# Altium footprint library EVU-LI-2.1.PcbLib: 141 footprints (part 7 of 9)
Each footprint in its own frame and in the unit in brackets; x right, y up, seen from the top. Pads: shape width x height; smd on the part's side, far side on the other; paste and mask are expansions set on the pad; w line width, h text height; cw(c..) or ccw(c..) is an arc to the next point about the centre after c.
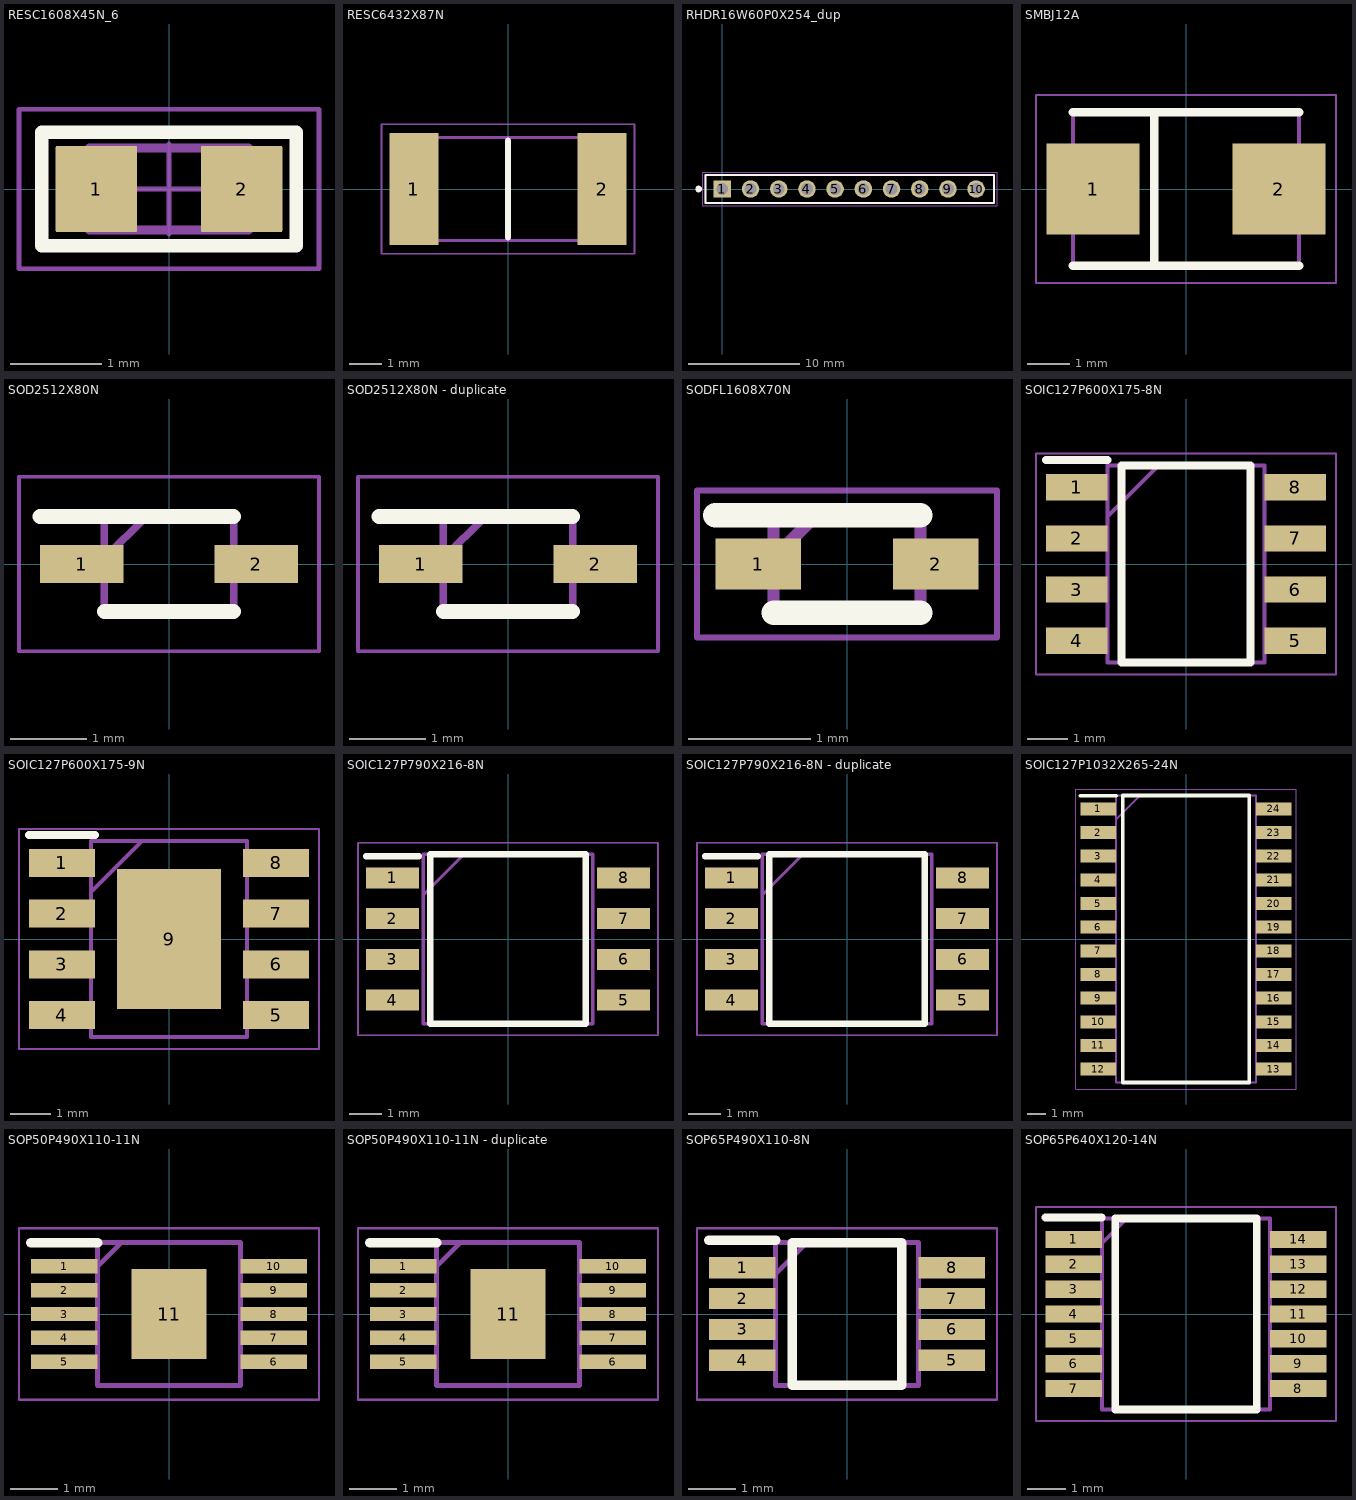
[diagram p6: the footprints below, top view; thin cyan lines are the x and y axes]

## RESC1608X45N_6 [mm]
pads (2):
  rrect5% 0.9x0.95 smd mask+0.07: 1(-0.8,0) 2(0.8,0)
Top Overlay:
  lines w0.15: -1.4,-0.625 1.4,-0.625 1.4,0.625 -1.4,0.625 -1.4,-0.625
Top Assembly:
  lines w0.1: -0.875,-0.45 -0.875,0.45 0.875,0.45 0.875,-0.45 -0.875,-0.45
Top Designator:
  text ".Designator" at -3.25,-0.3 h1.5
Mechanical 9:
  text ".MARK" at -1.725,-0.341 h1.2
Top Courtyard:
  lines w0.05: -0.5,0 0.5,0 ; 0,-0.5 0,0.5 ; -1.65,-0.875 -1.65,0.875 1.65,0.875 1.65,-0.875 -1.65,-0.875
3D body "RESC1608X06N.step": height 0.55, standoff 0, extent -0.85,-0.45 0.85,0.45

## RESC6432X87N [mm]
pads (2):
  rect 1.5x3.45 smd: 1(-2.9,0) 2(2.9,0)
Top Overlay:
  lines w0.2: 0,-1.49 0,1.49
Mechanical 13:
  lines w0.1: -3.175,-1.59 3.175,-1.59 3.175,1.59 -3.175,1.59 -3.175,-1.59
Top Courtyard:
  lines w0.05: -3.9,-2 3.9,-2 3.9,2 -3.9,2 -3.9,-2
3D body "TLR3APDTE10L0F50.stp": height 0.87, standoff 0, extent -3.175,-1.59 3.175,1.59

## RHDR16W60P0X254_dup [mm]
height 1.27
pads (10):
  rect 1.575x1.575 hole 1.05: 1(0,0)
  round 1.575 hole 1.05: 2(2.54,0) 3(5.08,0) 4(7.62,0) 5(10.16,0) 6(12.7,0) 7(15.24,0) 8(17.78,0) 9(20.32,0) 10(22.86,0)
Top Overlay:
  circle w0.3: c-2.134,0 r0.15
  lines w0.2: -1.52,-1.27 -1.52,1.27 24.46,1.27 24.46,-1.27 -1.473,-1.27
Assembly Notes:
  lines w0.1: -1.52,-1.27 -1.52,1.27 24.46,1.27 24.46,-1.27 -1.52,-1.27
Top Courtyard:
  lines w0.05: -1.77,-1.52 -1.77,1.52 24.74,1.52 24.74,-1.52 -1.77,-1.52
3D body "PBS-10.step": height 8.5, standoff -3, extent -1.469,-1.199 24.431,1.301

## SMBJ12A [mm]
pads (2):
  rect 2.2x2.15 smd: 1(-2.2,0) 2(2.2,0)
Top Overlay:
  lines w0.2: -2.675,-1.812 2.675,-1.812 ; -2.675,1.812 2.675,1.812 ; -0.75,-1.812 -0.75,1.812
Mechanical 13:
  lines w0.1: -2.675,-1.812 -2.675,1.812 2.675,1.812 2.675,-1.812 -2.675,-1.812
Top Courtyard:
  lines w0.05: -3.55,-2.225 -3.55,2.225 3.55,2.225 3.55,-2.225 -3.55,-2.225
3D body "SMBJ48A-TR.stp": height 2.33, standoff 0.01, extent -2.675,-1.86 2.675,1.86

## SOD2512X80N [mm]
pads (2):
  rect 1.1x0.5 smd: 1(-1.15,0) 2(1.15,0)
Top Overlay:
  lines w0.2: -1.7,0.625 0.85,0.625 ; -0.85,-0.625 0.85,-0.625
Mechanical 13:
  lines w0.1: -0.85,0.075 -0.3,0.625 ; -0.85,-0.625 -0.85,0.625 0.85,0.625 0.85,-0.625 -0.85,-0.625
Top Courtyard:
  lines w0.05: -1.975,-1.15 -1.975,1.15 1.975,1.15 1.975,-1.15 -1.975,-1.15
3D body "BZX84J-B4V7.stp": height 0.8, standoff 0, extent -1.25,-0.625 1.25,0.625

## SOD2512X80N - duplicate [mm]
pads (2):
  rect 1.1x0.5 smd: 1(-1.15,0) 2(1.15,0)
Top Overlay:
  lines w0.2: -1.7,0.625 0.85,0.625 ; -0.85,-0.625 0.85,-0.625
Mechanical 13:
  lines w0.1: -0.85,0.075 -0.3,0.625 ; -0.85,-0.625 0.85,-0.625 0.85,0.625 -0.85,0.625 -0.85,-0.625
Top Courtyard:
  lines w0.05: -1.975,-1.15 1.975,-1.15 1.975,1.15 -1.975,1.15 -1.975,-1.15
3D body "BZX84J-B4V7.stp": height 0.8, standoff 0, extent -1.25,-0.625 1.25,0.625

## SODFL1608X70N [mm]
pads (2):
  rect 0.7x0.42 smd: 1(-0.725,0) 2(0.725,0)
Top Overlay:
  lines w0.2: -1.075,0.4 0.6,0.4 ; -0.6,-0.4 0.6,-0.4
Mechanical 13:
  lines w0.1: -0.6,0.05 -0.25,0.4 ; -0.6,-0.4 -0.6,0.4 0.6,0.4 0.6,-0.4 -0.6,-0.4
Top Courtyard:
  lines w0.05: -1.225,-0.6 -1.225,0.6 1.225,0.6 1.225,-0.6 -1.225,-0.6
3D body "BAT30KFILM.stp": height 0.7, standoff 0, extent -0.8,-0.4 0.8,0.4

## SOIC127P600X175-8N [mm]
pads (8):
  rect 1.525x0.65 smd: 1(-2.712,1.905) 2(-2.712,0.635) 3(-2.712,-0.635) 4(-2.712,-1.905) 5(2.712,-1.905) 6(2.712,-0.635) 7(2.712,0.635) 8(2.712,1.905)
Top Overlay:
  lines w0.2: -3.475,2.58 -1.95,2.58 ; -1.6,-2.45 1.6,-2.45 1.6,2.45 -1.6,2.45 -1.6,-2.45
Mechanical 13:
  lines w0.1: -1.95,1.18 -0.68,2.45 ; -1.95,-2.45 1.95,-2.45 1.95,2.45 -1.95,2.45 -1.95,-2.45
Top Courtyard:
  lines w0.05: -3.725,-2.75 3.725,-2.75 3.725,2.75 -3.725,2.75 -3.725,-2.75
3D body "NE555DR.stp": height 1.75, standoff 0, extent -3,-2.45 3,2.45

## SOIC127P600X175-9N [mm]
pads (9):
  rect 1.65x0.7 smd: 1(-2.675,1.905) 2(-2.675,0.635) 3(-2.675,-0.635) 4(-2.675,-1.905) 5(2.675,-1.905) 6(2.675,-0.635) 7(2.675,0.635) 8(2.675,1.905)
  rect 2.6x3.5 smd: 9(0,0)
Top Overlay:
  lines w0.2: -3.5,2.605 -1.85,2.605
Mechanical 13:
  lines w0.1: -1.95,1.18 -0.68,2.45 ; -1.95,-2.45 -1.95,2.45 1.95,2.45 1.95,-2.45 -1.95,-2.45
Top Courtyard:
  lines w0.05: -3.75,-2.75 -3.75,2.75 3.75,2.75 3.75,-2.75 -3.75,-2.75
3D body "ST1S14PHR.stp": height 1.75, standoff 0, extent -3,-2.45 3,2.45

## SOIC127P790X216-8N [mm]
pads (8):
  rect 1.65x0.65 smd: 1(-3.6,1.905) 2(-3.6,0.635) 3(-3.6,-0.635) 4(-3.6,-1.905) 5(3.6,-1.905) 6(3.6,-0.635) 7(3.6,0.635) 8(3.6,1.905)
Top Overlay:
  lines w0.2: -4.425,2.58 -2.775,2.58 ; -2.425,-2.642 -2.425,2.642 2.425,2.642 2.425,-2.642 -2.425,-2.642
Mechanical 13:
  lines w0.1: -2.642,1.372 -1.372,2.642 ; -2.642,-2.642 -2.642,2.642 2.642,2.642 2.642,-2.642 -2.642,-2.642
Top Courtyard:
  lines w0.05: -4.675,-2.995 -4.675,2.995 4.675,2.995 4.675,-2.995 -4.675,-2.995
3D body "MT25QL128ABA1ESE-0SIT_TR.stp": height 2.16, standoff 0, extent -3.95,-2.642 3.95,2.642

## SOIC127P790X216-8N - duplicate [mm]
pads (8):
  rect 1.65x0.65 smd: 1(-3.6,1.905) 2(-3.6,0.635) 3(-3.6,-0.635) 4(-3.6,-1.905) 5(3.6,-1.905) 6(3.6,-0.635) 7(3.6,0.635) 8(3.6,1.905)
Top Overlay:
  lines w0.2: -4.425,2.58 -2.775,2.58 ; -2.425,-2.642 2.425,-2.642 2.425,2.642 -2.425,2.642 -2.425,-2.642
Mechanical 13:
  lines w0.1: -2.642,1.372 -1.372,2.642 ; -2.642,-2.642 2.642,-2.642 2.642,2.642 -2.642,2.642 -2.642,-2.642
Top Courtyard:
  lines w0.05: -4.675,-2.995 4.675,-2.995 4.675,2.995 -4.675,2.995 -4.675,-2.995
3D body "MT25QL128ABA1ESE-0SIT_TR.stp": height 2.16, standoff 0, extent -3.95,-2.642 3.95,2.642

## SOIC127P1032X265-24N [mm]
pads (24):
  rect 1.925x0.7 smd: 1(-4.712,6.985) 2(-4.712,5.715) 3(-4.712,4.445) 4(-4.712,3.175) 5(-4.712,1.905) 6(-4.712,0.635) 7(-4.712,-0.635) 8(-4.712,-1.905) 9(-4.712,-3.175) 10(-4.712,-4.445) 11(-4.712,-5.715) 12(-4.712,-6.985) 13(4.712,-6.985) 14(4.712,-5.715) 15(4.712,-4.445) 16(4.712,-3.175) 17(4.712,-1.905) 18(4.712,-0.635) 19(4.712,0.635) 20(4.712,1.905) 21(4.712,3.175) 22(4.712,4.445) 23(4.712,5.715) 24(4.712,6.985)
Top Overlay:
  lines w0.2: -5.675,7.685 -3.75,7.685 ; -3.4,-7.7 -3.4,7.7 3.4,7.7 3.4,-7.7 -3.4,-7.7
Mechanical 13:
  lines w0.1: -3.75,6.43 -2.48,7.7 ; -3.75,-7.7 -3.75,7.7 3.75,7.7 3.75,-7.7 -3.75,-7.7
Top Courtyard:
  lines w0.05: -5.925,-8.05 -5.925,8.05 5.925,8.05 5.925,-8.05 -5.925,-8.05
3D body "HIP4086ABZ.stp": height 2.65, standoff 0, extent -5.162,-7.7 5.162,7.7

## SOP50P490X110-11N [mm]
pads (11):
  rect 1.4x0.3 smd: 1(-2.2,1) 2(-2.2,0.5) 3(-2.2,0) 4(-2.2,-0.5) 5(-2.2,-1) 6(2.2,-1) 7(2.2,-0.5) 8(2.2,0) 9(2.2,0.5) 10(2.2,1)
  rect 1.57x1.88 smd: 11(0,0)
Top Overlay:
  lines w0.2: -2.9,1.5 -1.5,1.5
Mechanical 13:
  lines w0.1: -1.5,1 -1,1.5 ; -1.5,-1.5 -1.5,1.5 1.5,1.5 1.5,-1.5 -1.5,-1.5
Top Courtyard:
  lines w0.05: -3.15,-1.8 -3.15,1.8 3.15,1.8 3.15,-1.8 -3.15,-1.8
3D body "TPS54160DGQ.stp": height 0.96, standoff 0, extent -2.463,-1.5 2.463,1.5

## SOP50P490X110-11N - duplicate [mm]
pads (11):
  rect 1.4x0.3 smd: 1(-2.2,1) 2(-2.2,0.5) 3(-2.2,0) 4(-2.2,-0.5) 5(-2.2,-1) 6(2.2,-1) 7(2.2,-0.5) 8(2.2,0) 9(2.2,0.5) 10(2.2,1)
  rect 1.57x1.88 smd: 11(0,0)
Top Overlay:
  lines w0.2: -2.9,1.5 -1.5,1.5
Mechanical 13:
  lines w0.1: -1.5,1 -1,1.5 ; -1.5,-1.5 1.5,-1.5 1.5,1.5 -1.5,1.5 -1.5,-1.5
Top Courtyard:
  lines w0.05: -3.15,-1.8 3.15,-1.8 3.15,1.8 -3.15,1.8 -3.15,-1.8
3D body "TPS54160DGQ.stp": height 0.96, standoff 0, extent -2.463,-1.5 2.463,1.5

## SOP65P490X110-8N [mm]
pads (8):
  rect 1.4x0.45 smd: 1(-2.2,0.975) 2(-2.2,0.325) 3(-2.2,-0.325) 4(-2.2,-0.975) 5(2.2,-0.975) 6(2.2,-0.325) 7(2.2,0.325) 8(2.2,0.975)
Top Overlay:
  lines w0.2: -2.9,1.55 -1.5,1.55 ; -1.15,-1.5 -1.15,1.5 1.15,1.5 1.15,-1.5 -1.15,-1.5
Mechanical 13:
  lines w0.1: -1.5,0.85 -0.85,1.5 ; -1.5,-1.5 -1.5,1.5 1.5,1.5 1.5,-1.5 -1.5,-1.5
Top Courtyard:
  lines w0.05: -3.15,-1.8 -3.15,1.8 3.15,1.8 3.15,-1.8 -3.15,-1.8
3D body "ISL28246FUZ.stp": height 1.1, standoff 0, extent -2.45,-1.5 2.45,1.5

## SOP65P640X120-14N [mm]
pads (14):
  rect 1.475x0.45 smd: 1(-2.938,1.95) 2(-2.938,1.3) 3(-2.938,0.65) 4(-2.938,0) 5(-2.938,-0.65) 6(-2.938,-1.3) 7(-2.938,-1.95) 8(2.938,-1.95) 9(2.938,-1.3) 10(2.938,-0.65) 11(2.938,0) 12(2.938,0.65) 13(2.938,1.3) 14(2.938,1.95)
Top Overlay:
  lines w0.2: -3.675,2.525 -2.2,2.525 ; -1.85,-2.5 -1.85,2.5 1.85,2.5 1.85,-2.5 -1.85,-2.5
Mechanical 13:
  lines w0.1: -2.2,1.85 -1.55,2.5 ; -2.2,-2.5 -2.2,2.5 2.2,2.5 2.2,-2.5 -2.2,-2.5
Top Courtyard:
  lines w0.05: -3.925,-2.8 -3.925,2.8 3.925,2.8 3.925,-2.8 -3.925,-2.8
3D body "TSV994IPT.stp": height 1.2, standoff 0, extent -3.2,-2.5 3.2,2.5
